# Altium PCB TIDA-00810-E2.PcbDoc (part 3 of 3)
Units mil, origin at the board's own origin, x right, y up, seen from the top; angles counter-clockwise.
Board outline 4527.56 x 3740.16 mil, 4 copper layers (Top Layer, Signal Layer 1, Signal Layer 2, Bottom Layer), stack 25.634 mil thick; 448 components, 198 nets, 1031 pads, 344 vias.
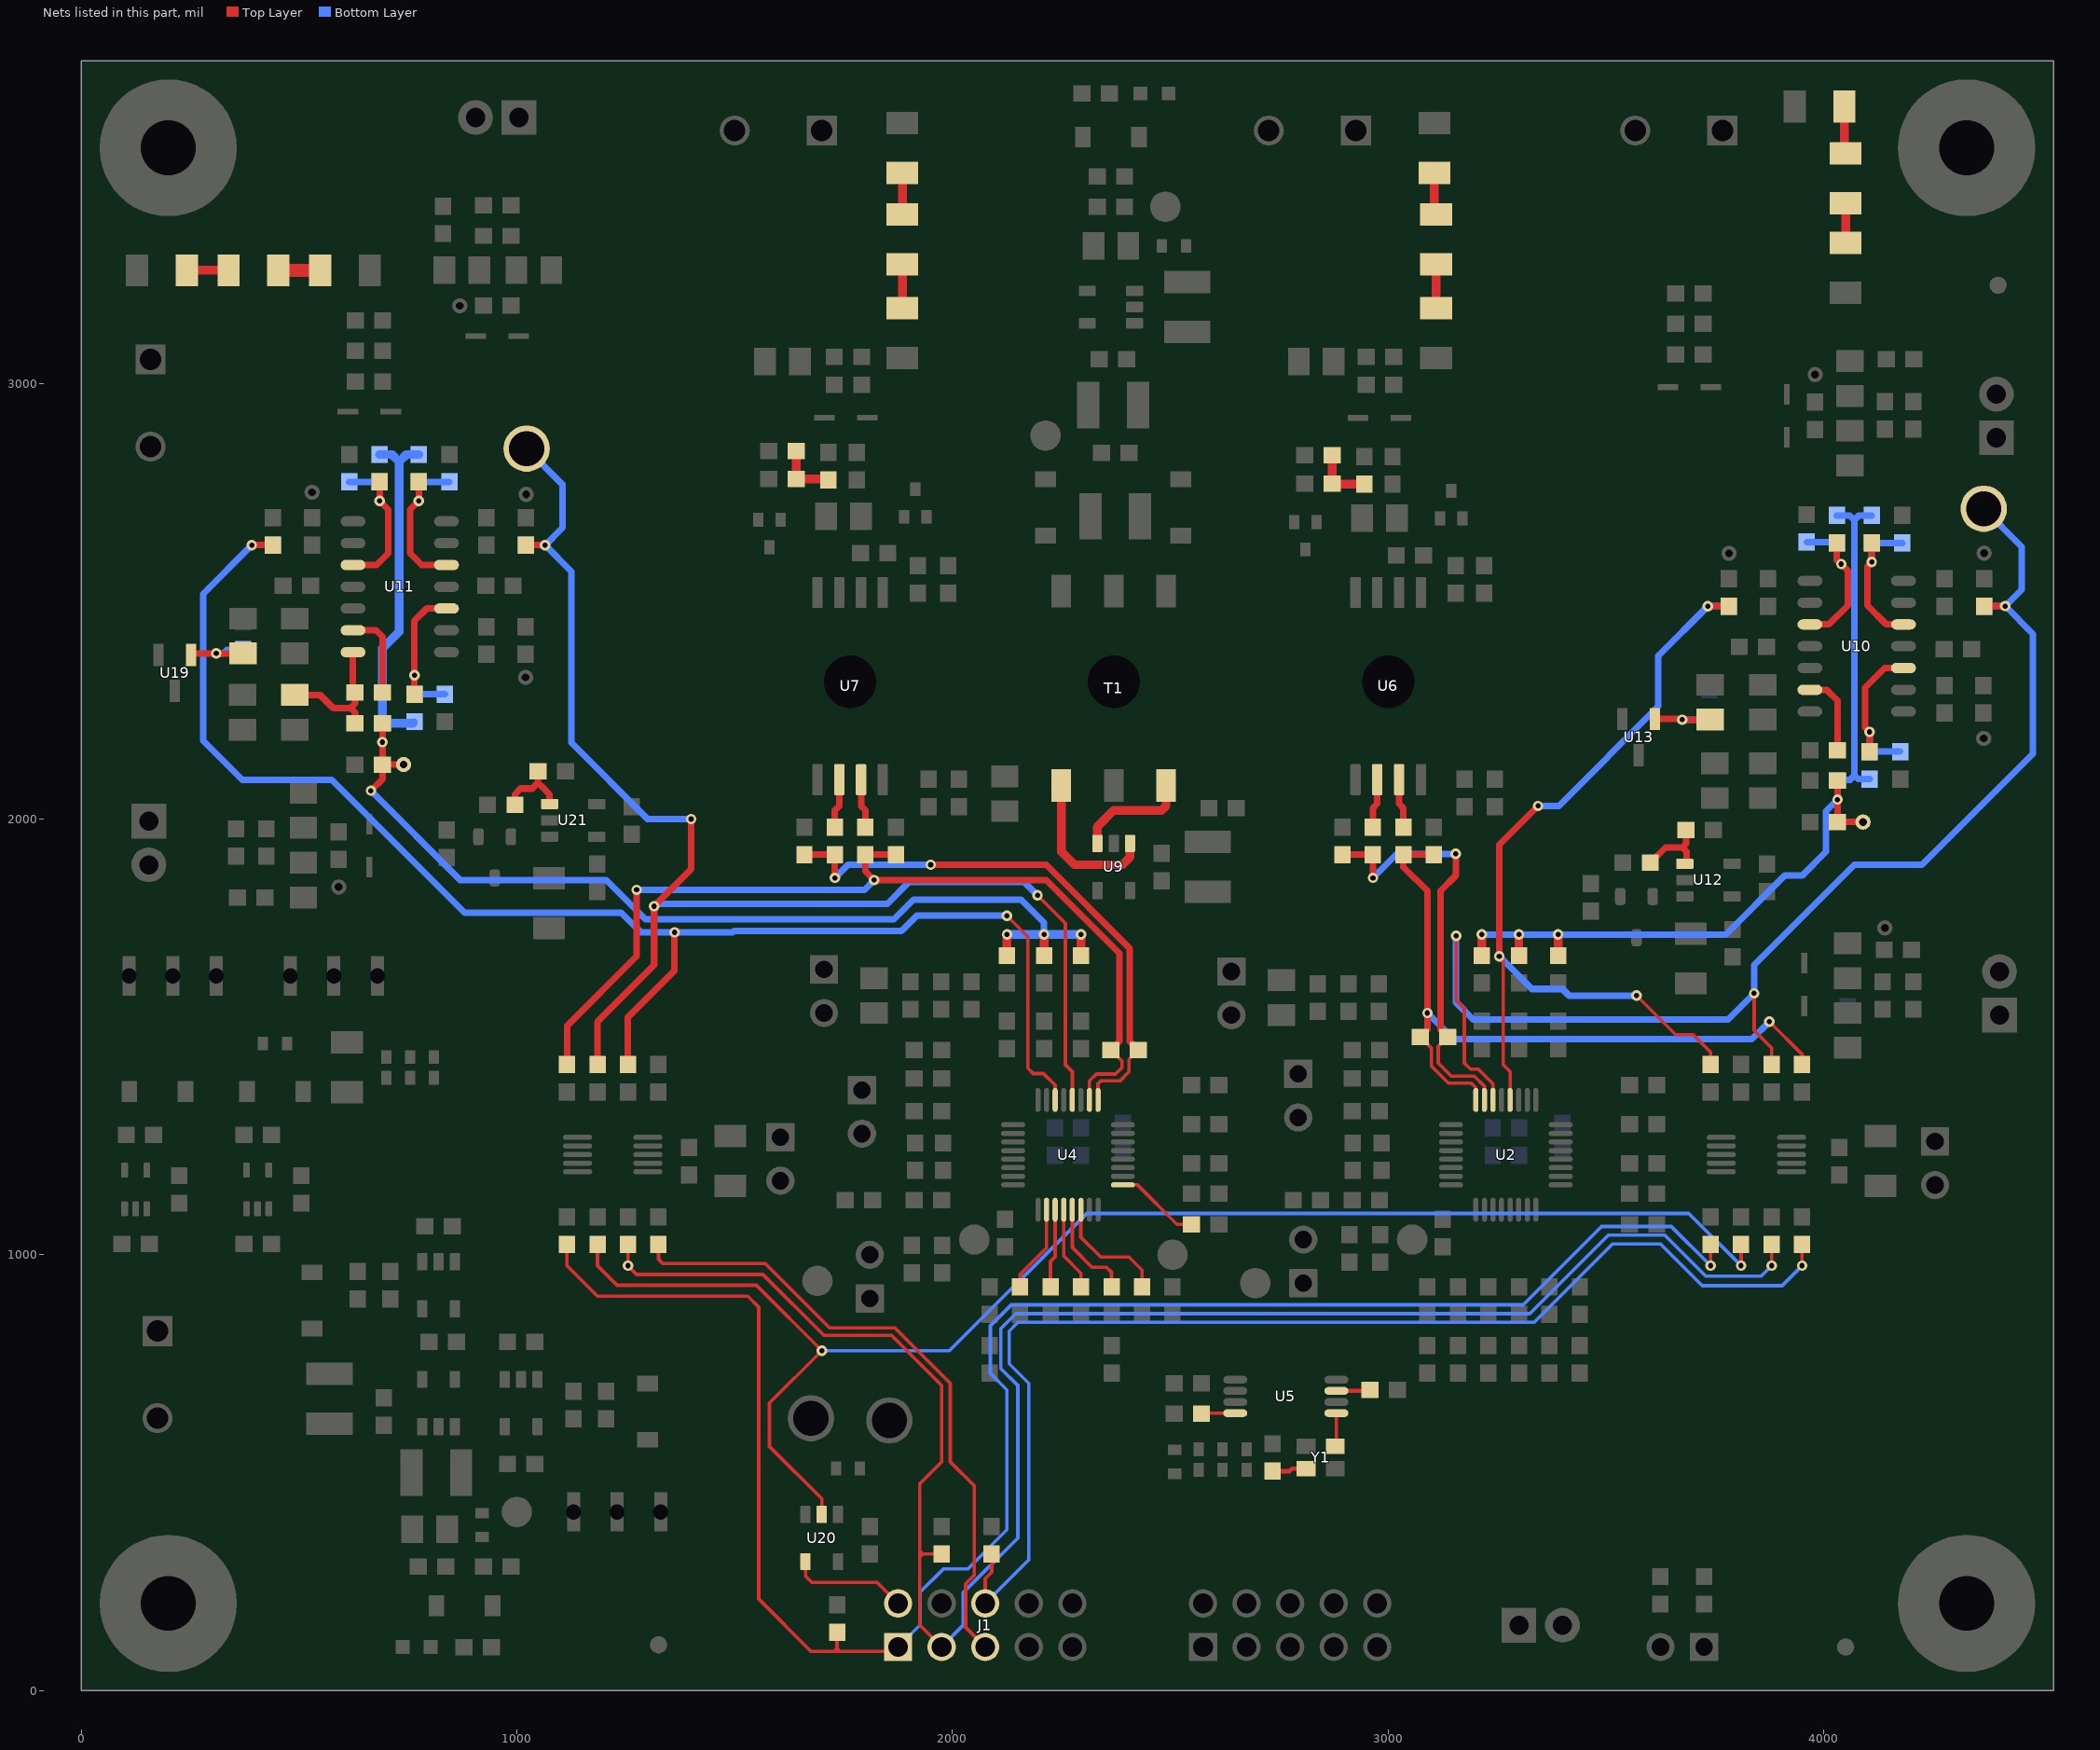
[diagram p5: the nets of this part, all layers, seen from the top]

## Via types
v1: diameter 24, hole 12, Top Layer to Bottom Layer, tented both sides, 309 vias
v2: diameter 32, hole 16, Top Layer to Bottom Layer, tented both sides, 35 vias

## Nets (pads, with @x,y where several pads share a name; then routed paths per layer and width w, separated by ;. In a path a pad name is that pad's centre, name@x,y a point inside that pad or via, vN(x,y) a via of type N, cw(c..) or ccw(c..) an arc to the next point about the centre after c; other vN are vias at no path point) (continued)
NetR39_2: R39.2 U4.22 | length 273.1
  Top Layer w8: U4.22@2294.59,1103.36 2294.59,1040.47 2340.06,995 2405,995 2435.07,964.93 R39.2@2435.07,926.49
NetR40_2: R40.2 U4.20 | length 193.4
  Top Layer w8: U4.20@2255.22,1103.36 2255.22,997.34 2295.07,957.5 R40.2@2295.07,926.49
NetR41_2: R41.2 U4.21 | length 247.1
  Top Layer w8: 2274.91,1030 2274.91,1016.65 ; U4.21@2274.91,1103.36 2274.91,1016.65 ; R41.2@2365.07,926.49 2365.07,959.93 2353.43,971.57 2319.99,971.57 2274.91,1016.65
NetR42_2: R42.2 U4.19 | length 181.2
  Top Layer w8: R42.2@2225.07,926.49 2225.07,949.18 2225.07,985 2235.54,995.47 2235.54,1000.47 2235.54,1010.47 U4.19@2235.54,1103.36
NetR43_2: R43.2 U4.18 | length 215.4
  Top Layer w8: R43.2@2155.07,930 R43.2@2155.07,926.49 2155.07,955 2165.07,965 ; 2158.12,958.05 2215.85,1015.79 U4.18@2215.85,1103.36
NetR44_1: R44.1 U4.25 | length 195
  Top Layer w8: U4.25@2391.05,1160.44 2424.62,1160.44 2515.07,1070 R44.1@2548.57,1070
NetR47_2: R47.2 U5.3 | length 81.4
  Top Layer w10: U5.3@2881.14,687.8 2881.35,688 2956.5,688 R47.2@2958.5,690 R47.2@2956.3,687.8
NetR48_2: R48.2 U5.8 | length 78
  Top Layer w8: R48.2@2571.5,635 2573.11,636.61 U5.8@2648.86,636.61
NetR49_2: R49.2 Y1.1 | length 79
  Top Layer w10: R49.2@2735,503.5 2773.5,503.5 2779.41,509.41 Y1.1@2811.54,509.41
NetR51_2: R51.2 R52.1 | length 98.6
  Top Layer w20: R51.2@3105.96,3493.98 3105.96,3401.12 R52.1@3110,3397.09
NetR52_2: R52.2 R53.1 | length 105.8
  Top Layer w20: R53.1@3110,3177.09 R52.2@3110,3282.91
NetR57_1: R57.1 U6.7 | length 113.1
  Top Layer w15: U6.7@3025,2090.43 3025,2035 3035,2025 R57.1@3035,1981.5
NetR58_1: R58.1 U6.6 | length 113.1
  Top Layer w15: R58.1@2965,1981.5 2965,2025 2975,2035 U6.6@2975,2090.43
NetR60_2: R60.2 R180.2 R184.2 | length 139.1
  Top Layer w20: R184.2@2871.5,2835 R180.2@2871.5,2770 2872.99,2768.5 R60.2@2945,2768.5
NetR61_2: R61.2 R62.1 | length 95.8
  Top Layer w20: R62.1@1885,3387.09 R61.2@1885,3482.91
NetR62_2: R62.2 R63.1 | length 100.8
  Top Layer w20: R63.1@1885,3172.09 R62.2@1885,3272.91
NetR66_1: R66.1 U7.7 | length 113.1
  Top Layer w15: U7.7@1790,2090.43 1790,2030 1800,2020 R66.1@1800,1981.5
NetR69_1: R69.1 U7.6 | length 113.1
  Top Layer w15: R69.1@1730,1981.5 1730,2020 1740,2030 U7.6@1740,2090.43
NetR71_2: R71.2 R181.2 R185.2 | length 139.1
  Top Layer w20: R185.2@1641.5,2845 R181.2@1641.5,2780 1713.5,2780 R71.2@1715,2778.5
NetR74_1: R74.1 R78.2 | length 109.1
  Top Layer w20: R74.1@4047.09,3635 4047.09,3530 R78.2@4050,3527.09
NetR76_1: R76.1 R80.2 | length 95.8
  Top Layer w20: R76.1@242.46,3259.39 R80.2@338.29,3259.39
NetR78_1: R78.1 R84.2 | length 90.8
  Top Layer w20: R84.2@4050,3322.09 R78.1@4050,3412.91
NetR80_1: R80.1 R87.2 | length 95.8
  Top Layer w30: R80.1@452.46,3259.39 R87.2@548.29,3259.39
NetR85_1: R85.1 R130.2 R178.2 U10.10 | length 381.1
  Top Layer w15: U10.10@3968.18,2446.56 4011.56,2446.56 4055,2490 4055,2570 v1(4040,2585) 4030,2595 R85.1@4030,2633.5
  Bottom Layer w15: R178.2@3961,2635.5 4028,2635.5 R130.2@4030,2633.5 4030,2595 v1(4040,2585)
NetR86_1: R86.1 R131.2 R179.2 U11.10 | length 377.6
  Top Layer w15: U11.10@623.88,2583.03 678.03,2583.03 705,2610 705,2710 v1(685,2730) R86.1@685,2773.5
  Bottom Layer w15: R179.2@615,2773.5 R131.2@685,2773.5 v1(685,2730)
NetR98_1: R98.1 R168.2 R174.2 U10.3 | length 373
  Top Layer w15: R98.1@4105,2154.57 v1(4105,2200) 4095,2210 4095,2301.56 4140,2346.56 U10.3@4182.75,2346.56
  Bottom Layer w15: v1(4105,2200) R168.2@4105,2154.57 R174.2@4175,2154.57
NetR99_1: R99.1 R169.2 R175.2 U11.3 | length 367.1
  Top Layer w15: R99.1@765,2286.5 v1(765,2330) 765,2455 793.03,2483.03 U11.3@838.45,2483.03
  Bottom Layer w15: v1(765,2330) R169.2@765,2286.5 R175.2@835,2286.5
NetR114_1: R114.1 R172.2 R176.2 U10.5 | length 361.9
  Top Layer w15: R114.1@4110,2633.5 v1(4110,2590) 4100,2580 4100,2490 4143.44,2446.56 U10.5@4182.75,2446.56
  Bottom Layer w15: v1(4110,2590) R172.2@4110,2633.5 R176.2@4180,2633.5
NetR115_1: R115.1 R173.2 R177.2 U11.5 | length 379.9
  Top Layer w15: R115.1@775,2773.5 v1(775,2730) 755,2710 755,2610 781.97,2583.03 U11.5@838.45,2583.03
  Bottom Layer w15: v1(775,2730) R173.2@775,2773.5 R177.2@845,2773.5
NetR116_1: R116.1 U10.13 | length 187.2
  Top Layer w15: U10.13@3968.18,2296.56 4006.51,2296.56 4031.5,2271.58 R116.1@4031.5,2158.07
NetR117_1: R117.1 U11.13 | length 202.1
  Top Layer w15: U11.13@623.88,2433.03 676.97,2433.03 691.5,2418.5 R117.1@691.5,2290
NetR117_2: R117.2 R129.1 R139.2 U11.14 | length 317.1
  Top Layer w15: R139.2@490,2285 548,2285 578,2255 621,2255 ; U11.14@623.88,2383.03 623.88,2294.62 R117.2@628.5,2290 628.5,2265.5 618,2255 628.5,2244.5 R129.1@628.5,2220
NetR119_2: R119.2 R127.2 U12.1 | length 175
  Top Layer w15: R127.2@3601.5,1900 3636.5,1935 3675,1935 ; U12.1@3680.87,1897.4 3685,1901.54 3685,1925 3675,1935 ; R119.2@3683.5,1975 3683.5,1943.5 3675,1935
NetR120_1: R120.1 R128.2 U21.1 | length 181.1
  Top Layer w15: R128.2@995.63,2032.05 995.63,2056.81 1008.82,2070 1035,2070 1048.5,2083.5 ; R120.1@1048.5,2110 1048.5,2083.5 ; U21.1@1079.13,2038.58 U21.1@1075,2034.45 1075,2057 1062.01,2069.99 1048.5,2083.5
NetR152_1: R152.1 R153.1 U13.1 | length 191.2
  Top Layer w15: U13.1@3612.4,2229.41 3673.66,2229.41 v1(3675,2228.07) R153.1@3738.62,2228.07
  Bottom Layer w15: v1(3675,2228.07) 3732.09,2228.07 R152.1@3737.3,2233.29
NetR155_1: R155.1 R156.1 U19.1 | length 185.6
  Top Layer w15: U19.1@252.4,2376.34 256.06,2380 v1(310,2380) R156.1@371.46,2380
  Bottom Layer w15: v1(310,2380) 326.46,2380 334.96,2388.5 R155.1@371.46,2388.5
NetT1_1: T1.1 U9.1 | length 361.2
  Top Layer w20: T1.1@2249.92,2077.36 2249.92,1925.08 2280,1895 2390,1895 2407.4,1912.4 U9.1@2407.4,1944.13
NetT1_3: T1.3 U9.3 | length 262.9
  Top Layer w20: U9.3@2332.6,1944.13 2332.6,1982.6 2370,2020 2480,2020 2490.08,2030.08 T1.3@2490.08,2077.36
NetU5_1: U5.1 Y1.3 | length 77.1
  Top Layer w8: Y1.3@2878.46,560.59 2881.14,563.27 U5.1@2881.14,636.61
PD_OUT1: C57.1 R81.2 R144.2 U2.4 | length 2071.1
  Top Layer w8: v1(3255,1685) 3264,1676 3264,1436.06 3279.91,1420.16 U2.4@3279.91,1355.33 ; v1(3570,1595) 3660,1505 3700,1505 3740.13,1464.87 R144.2@3740.13,1436.49
  Top Layer w15: v1(3255,1685) 3255,1941 v1(3344,2030) ; v1(3733.8,2488.29) R81.2@3782.3,2488.29
  Bottom Layer w15: v1(3255,1685) 3330,1610 3400,1610 3415,1595 v1(3570,1595) ; v1(3344,2030) 3391.5,2030 3620,2258.5 3620,2374.49 v1(3733.8,2488.29) C57.1@3782.3,2488.29
PD_OUT2: C58.1 R83.2 R150.2 U4.6 | length 3467
  Top Layer w8: v1(2125,1778) 2173,1730 2173,1428 2185,1416 2209,1416 2235.54,1389.46 U4.6@2235.54,1355.33
  Top Layer w15: v1(391.5,2628.5) R83.2@440,2628.5 ; R150.2@1255.07,1436.49 1255.07,1545.07 1362,1652 v1(1362,1740) v1@1362,1742
  Bottom Layer w15: C58.1@440,2628.5 v1(391.5,2628.5) 280,2517.01 280,2180 370,2090 575,2090 880,1785 1240,1785 1285,1740 v1(1362,1740) 1495.47,1740 1498.47,1743 1883,1743 1918,1778 v1(2125,1778)
ROGO_1_OUT: C74.1 R111.2 R146.2 TP4.1 U2.6 | length 3123.3
  Top Layer w8: v1(3156,1732) 3156,1584 3175,1565 3175,1440 3189,1426 3207.07,1426 3240.54,1392.53 U2.6@3240.54,1355.33 ; v1(3840,1600) 3840,1515 3880.13,1474.87 R146.2@3880.13,1436.49
  Top Layer w15: R111.2@4367.87,2488.5 v1(4416.37,2488.5)
  Bottom Layer w15: v1(3156,1732) 3156,1579 3195,1540 3780,1540 v1(3840,1600) 3840,1665 4070,1895 4225,1895 4480,2150 4480,2424.88 v1(4416.37,2488.5) ; TP4.1@4367,2712 4454,2625 4454,2526.13 v1(4416.37,2488.5) ; C74.1@4367.87,2488.5 v1(4416.37,2488.5)
ROGO_2_OUT: C75.1 R113.2 R147.2 TP8.1 U4.4 | length 3255.8
  Top Layer w8: v1(2195,1825) 2259,1761 2259,1436.06 2274.91,1420.16 U4.4@2274.91,1355.33
  Top Layer w15: R113.2@1021.32,2628.5 v1(1064.82,2628.5) ; R147.2@1185.07,1436.49 1185.07,1535.07 1315,1665 v1(1315,1800) 1400,1885 v1(1400,2000)
  Bottom Layer w15: C75.1@1021.32,2628.5 v1(1064.82,2628.5) ; TP8.1@1022.5,2850 1105,2767.5 1105,2668.68 v1(1064.82,2628.5) ; v1(1315,1800) 1320,1805 1850,1805 1900,1855 2165,1855 v1(2195,1825) ; v1(1400,2000) 1300,2000 1125,2175 1125,2568.33 v1(1064.82,2628.5)
SAR1_CS#: J1.6 R4.2 R162.1 | length 2815
  Top Layer w8: J1.6@2075,200 2075,256.75 2090,271.75 R162.1@2090,313.5 ; v1(3950.07,975) R4.2@3950.07,1023.5
  Bottom Layer w8: J1.6@2075,200 2175,300 2175,705 2130,750 2130,825 2150,845 3335,845 3515,1025 3625,1025 3721,929 3904.07,929 v1(3950.07,975)
SAR2_CS#: J1.5 R27.2 | length 1476.3
  Top Layer w8: R27.2@1325,1023.5 1325,990 1335,980 1570,980 1717.5,832.5 1867.5,832.5 1995,705 1995,525 2050,470 2050,265 2030,245 2030,145 J1.5@2075,100
SAR_DIN: J1.3 R1.2 R24.2 R163.1 | length 4360.5
  Top Layer w8: R24.2@1255,1023.5 v1(1255,975) 1275,955 1565,955 1705,815 1860,815 1975,700 1975,525 1925,475 1925,150 J1.3@1975,100 ; 1925,307.01 1931.5,313.5 ; 1925,320 1931.5,313.5 ; R163.1@1975,313.5 1931.5,313.5 ; v1(3880.07,975) R1.2@3880.07,1023.5
  Bottom Layer w8: v1(1255,975) v1(1255,975) ; J1.3@1975,100 2024,149 2024,224 2150,350 2150,700 2111,739 2111,831 2145,865 3325,865 3505,1045 3635,1045 3729.03,950.97 3856.03,950.97 v1(3880.07,975)
SAR_DOUT: R2.1 R25.1 U20.2 | length 3458.3
  Top Layer w8: R25.1@1185.07,1023.5 1185.07,974.93 1230,930 1550,930 v1(1700,780) 1580,660 1580,560 1700,440 U20.2@1700,404.13 ; v1(3810.07,975) R2.1@3810.07,1023.5
  Bottom Layer w8: v1(1700,780) 1993,780 2308,1095 3690.06,1095 v1(3810.07,975)
SAR_DOUT_L: J1.2 U20.4 | length 271.7
  Top Layer w8: U20.4@1662.6,295.87 1662.6,262.4 1677,248 1827,248 J1.2@1875,200
SAR_SCLK: J1.1 R3.2 R26.2 R140.1 | length 4350.4
  Top Layer w8: R26.2@1115,1023.5 1115,975 1185,905 1530,905 1555,880 1555,210 1675,90 1728,90 ; R140.1@1735,133.5 1735,97 ; J1.1@1875,100 1865,90 1742,90 ; v1(3740.07,975) R3.2@3740.07,1023.5 ; 1728,90 1742,90 ; 1728,90 1735,97 ; 1735,97 1742,90
  Bottom Layer w8: J1.1@1875,100 1926,151 1926,226 1979,279 2035,279 2125,369 2125,690 2087,728 2087,837 2135,885 3310,885 3490,1065 3650,1065 v1(3740.07,975) v1(3740.07,975)
VOUT1_N: C105.1 C110.1 R58.2 U2.7 | length 1006
  Top Layer w8: C105.1@3136.56,1500 3115.07,1478.5 3115.07,1439.93 3145,1410 3197.69,1410 3220.98,1386.71 3220.85,1386.58 U2.7@3220.85,1355.33
  Top Layer w15: C110.1@2895,1918.5 R58.2@2965,1918.5 v1(2965,1865) ; C105.1@3136.56,1500 3120,1516.56 3120,1835 3155,1870 v1(3155,1920)
  Bottom Layer w15: v1(2965,1865) 3020,1920 v1(3155,1920)
VOUT1_P: C105.2 C111.1 R57.2 R145.2 U2.8 | length 1702.5
  Top Layer w8: C105.2@3073.57,1500 3099.07,1474.5 3099.07,1433.31 3138.37,1394 3191.07,1394 3201.17,1383.9 U2.8@3201.17,1355.33 ; v1(3875,1535) 3950.13,1459.87 R145.2@3950.13,1436.49
  Top Layer w15: C105.2@3073.57,1500 3090,1516.43 v1(3090,1555) 3090,1835 3035,1890 R57.2@3035,1918.5 C111.1@3105,1918.5
  Bottom Layer w15: v1(3090,1555) 3150,1495 3835,1495 v1(3875,1535)
VOUT2_N: C106.1 C112.1 R69.2 U4.1 | length 1312.4
  Top Layer w8: U4.1@2333.96,1355.33 2333.96,1392.9 2340.07,1399 2384.07,1399 2405.07,1420 2405.07,1448.5 C106.1@2426.56,1470
  Top Layer w15: C112.1@1660,1918.5 R69.2@1730,1918.5 v1(1730,1865) ; v1(1950,1895) 2215,1895 2407.13,1702.87 2407.13,1489.43 C106.1@2426.56,1470
  Bottom Layer w15: v1(1730,1865) 1760,1895 v1(1950,1895)
VOUT2_P: C106.2 C113.1 R66.2 R148.2 U4.2 | length 2205.6
  Top Layer w8: U4.2@2314.28,1355.33 2314.28,1399.21 2330.07,1415 2374.07,1415 2389.07,1430 2389.07,1444.5 C106.2@2363.57,1470
  Top Layer w15: R148.2@1115.07,1436.49 1115.07,1525.07 1275,1685 v1(1275,1837.63) ; C113.1@1870,1918.5 R66.2@1800,1918.5 1800,1880 v1(1820,1860) 2215,1860 2383,1692 2383,1489.43 C106.2@2363.57,1470 C106.2@2363.57,1472.57
  Bottom Layer w15: v1(1275,1837.63) 1797.63,1837.63 v1(1820,1860)
VREF_ADC1: C76.2 R118.1 R126.2 R130.1 R136.1 R137.1 R138.1 R168.1 R172.1 TP21.1 | length 2100.5
  Top Layer w15: R118.1@4030,1991.58 R118.1@4031.5,1993.07 ; R126.2@4031.5,2088.07 v1(4031.5,2044.57) R118.1@4031.5,1993.07 ; TP21.1@4090,1993.07 R118.1@4031.5,1993.07
  Top Layer w20: R138.1@3215.07,1686.5 v1(3215.07,1735) ; R137.1@3300.07,1686.5 v1(3300.07,1735) ; R136.1@3390.07,1686.5 v1(3390.07,1735)
  Bottom Layer w15: v1(3215.07,1735) v1(3300.07,1735) v1(3390.07,1735) 3775,1735 3910,1870 3950,1870 4005,1925 4005,2018.07 v1(4031.5,2044.57) C76.2@4031.5,2088.07 4033.42,2090 4060,2090 4070,2100 ; R130.1@4030,2696.5 4059.7,2696.5 4070,2686.2 ; R168.1@4105,2091.58 4078.42,2091.58 4070,2100 ; R172.1@4110,2696.5 4080.3,2696.5 4070,2686.2 ; 4070,2100 4070,2686.2
VREF_ADC2: C77.2 R121.1 R129.2 R131.1 R158.1 R159.1 R160.1 R169.1 R173.1 TP22.1 | length 3105.1
  Top Layer w15: v1(665,2065) 691.5,2091.5 R121.1@691.5,2125 ; R129.2@691.5,2220 v1(691.5,2176.5) R121.1@691.5,2125 ; TP22.1@740,2125 R121.1@691.5,2125
  Top Layer w20: R160.1@2125.07,1686.5 v1(2125.07,1735) ; R159.1@2210.07,1686.5 v1(2210.07,1735) ; R158.1@2295.07,1686.5 v1(2295.07,1735)
  Bottom Layer w15: v1(665,2065) 870,1860 1205,1860 1295,1770 1865,1770 1910,1815 2157.3,1815 2210.07,1762.23 v1(2210.07,1735) ; v1(691.5,2176.5) C77.2@691.5,2220 ; R169.1@761.5,2220 765,2220 R169.1@765,2223.5
  Bottom Layer w20: R131.1@685,2836.5 713.5,2836.5 730,2820 ; R169.1@761.5,2220 C77.2@691.5,2220 691.5,2391.5 730,2430 730,2820 ; R173.1@775,2836.5 746.5,2836.5 730,2820 ; v1(2125.07,1735) v1(2210.07,1735) v1(2295.07,1735)
pads on no net: D1.3 D2.3 D3.3 D4.3 D5.3 D6.3 D7.3 D8.3 D13.2 D14.2 FID1.1 FID2.1 FID3.1 FID4.1 FID5.1 FID6.1 H1.1 H2.1 H3.1 H4.1 H5.0 H6.0 H7.0 H8.0 J1.8 LBL1.0 U2.24 U2.26 U4.24 U4.26 U5.5 U5.7 U8.4 U8.5 U13.3 U14.4 U14.5 U19.3 U20.1

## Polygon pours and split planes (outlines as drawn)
-2P5V on Top Layer "-2P5V_L01_P024" (solid, remove dead copper, pour order 24): 1010,630 1020,640 1355,640 1370,625 1370,560 1370,540 1355,525 1125,525 1085,565 1020,565 1010,575
3.3V on Top Layer "3.3V_L01_P006" (solid, remove dead copper, pour order 6): 325,1435 340,1450 385,1450 395,1440 395,1210 395,1170 385,1160 335,1160 325,1170
AGND on Top Layer "AGND_L01_P010" (solid, remove dead copper, pour order 10): 870,1400 855,1415 710,1415 685,1415 680,1420 470,1420 460,1410 460,1340 450,1330 430,1330 420,1320 420,1245 425,1240 470,1240 560,1240 570,1230 570,1160 555,1145 470,1145 460,1135 460,1080 450,1070 430,1070 420,1060 420,1025 420,1003 420,980 430,970 460,970 500,1010 625,1010 635,1020 635,1230 645,1240 855,1240 870,1255
+5V on Top Layer "+5V_L01_P020" (solid, remove dead copper, pour order 20): 970,250 915,250 900,235 900,150 915,135 1040,135 1060,155 1060,330 1050,340 980,340 970,330
NetC80_2 on Top Layer "NETC80_2_L01_P016" (solid, remove dead copper, pour order 16): 850,645 850,440 860,430 925,430 935,440 935,635 915,655 860,655
AGND on Top Layer "AGND_L01_P014" (solid, remove dead copper, pour order 14): 50,683.62 71.37,705 375,705 415,665 630,665 650,645 650,625 780,625 790,615 790,590 790,575 775,560 775,510 775,330 780,325 790,315 790,285 790,250 795,245 855,245 860,240 860,150 850,140 770,140 760,140 680,140 500,140 475,165 475,220 475,450 450,475 445,480 280,480 70,480 50,500
+2P5V on Top Layer "+2P5V_L01_P012" (solid, remove dead copper, pour order 12): 50,1442.05 62.95,1455 125,1455 160,1455 165,1450 165,1365 125,1325 125,1175 110,1160 60,1160 50,1170
AVCC_3.3 on Top Layer "AVCC_3.3_L01_P008" (solid, remove dead copper, pour order 8): 540,1535 555,1550 845,1550 865,1530 865,1450 855,1440 695,1440 670,1440 550,1440 540,1450
DC_IN on Top Layer "DC_IN_L01_P000" (solid, remove dead copper, pour order 0): 103,1117 103,1047 110,1040 110,965 135,940 230,940 320,940 330,950 330,1120 340,1130 380.01,1130 390,1120.01 390,945 410,925 510,925 565,870 565,855 665,755 690,730 715,730 765,680 830,680 835,675 835,655 830,650 745,650 675,650 645,680 440,680 365,755 65,755 50,770 50,1115 60,1125 95,1125
AGND on Top Layer "AGND_L01_P004" (solid, remove dead copper, pour order 4): 572.5,912.5 580,920 795,920 800,915 800,830 815,815 815,765 805,755 705,755 572.5,887.5
AGND on Top Layer "AGND_L01_P002" (solid, remove dead copper, pour order 2): 195,1440 195,1340 185,1330 160,1330 150,1320 150,1239.99 160,1230 260,1230 270,1220 270,1160 250,1140 190,1140 180,1130 180,1070 175,1065 145,1065 135,1055 135,1030 135,975 145,965 295,965 305,975 305,1440 290,1455 210,1455
NetC94_1 on Top Layer "NETC94_1_L01_P022" (solid, remove dead copper, pour order 22): 995,840 995,765 1020,740 1020,675 1010,665 940,665 915,690 915,740 905,750 850,750 840,760 840,825 865,850 985,850
AGND on Top Layer "AGND_L01_P026" (solid, remove dead copper, pour order 26): 1020,840 1020,775 1040,755 1040,675 1050,665 1355,665 1370,680 1370,845 1365,850 1030,850
AVSS on Bottom Layer "AVSS_L04_P028" (solid, remove dead copper, pour order 28): 1700,1200 1790,1110 2110,1110 2140,1110 2163.7,1133.7 2163.69,1313.69 2178.84,1328.84 2338.84,1328.84 2470,1460 2660,1460 2685,1435 2685,1205 2740,1150 3155,1150 3165,1160 3165,1310 3183.84,1328.84 3353.84,1328.84 3385,1360 3385,1420 3365,1440 3145,1440 3060,1525 3060,1695 3015,1740 2360,1740 2260,1640 1890,1640 1700,1450
GND_VDC on Signal Layer 1 "GND_VDC_L02_P030" (solid, remove dead copper, pour order 30): 1400,3675 1425,3700 1700,3700 3250,3700 3275,3675 3275,2500 3250,2475 3125,2475 1425,2475 1400,2500 1400,3675
AGND on Signal Layer 1 "AGND_L02_P038" (solid, remove dead copper, pour order 38): 50,3300 75,3325 350,3325 375,3325 400,3350 400,3675 425,3700 625,3700 1150,3700 1175,3675 1175,3550 1175,2150 1200,2125 1325,2125 3450,2125 3475,2150 3475,2225 3475,3675 3500,3700 3650,3700 4100,3700 4125,3675 4125,3600 4125,3375 4150,3350 4175,3325 4300,3325 4450,3325 4475,3300 4475,3150 4475,425 4450,400 4425,400 4125,400 4100,375 4100,175 4100,75 4075,50 3800,50 3600,50 3575,75 3575,475 3625,525 3625,875 3600,900 3600,1425 3575,1450 3440,1450 3300,1310 3300,1210 3260,1170 3160,1170 3115,1125 3050,1125 2625,1125 2600,1150 2600,1450 2575,1475 2550,1475 2460,1475 2317.5,1332.5 2295,1310 2295,1190 2265,1160 2145,1160 1960,1160 1950,1150 1850,1050 1850,975 1850,900 1775,825 1750,800 1750,625 1750,75 1725,50 1350,50 450,50 425,75 425,250 425,400 400,425 225,425 75,425 50,450
GND on Signal Layer 1 "GND_L02_P034" (solid, remove dead copper, pour order 34): 2465,1450 2550,1450 2575,1425 2575,1150 2625,1100 3125,1100 3170,1145 3274.87,1145 3325,1195.13 3325,1300 3450,1425 3575,1425 3575,1235 3575,875 3600,850 3600,550 3550,500 3550,375 3550,250 3550,75 3525,50 3275,50 3075,250 2380,250 2360,230 2360,160 2350,150 2250,150 2225,175 2225,225 2200,250 1800,250 1775,275 1775,800 1850,875 1875,900 1875,1025 1985,1135 2150,1135 2280,1135 2320,1175 2320,1305
+5.0V_VDC on Signal Layer 2 "+5.0V_VDC_L03_P032" (solid, remove dead copper, pour order 32): 1450,3550 1450,3625 1475,3650 1575,3650 3200,3650 3225,3625 3225,3550 3225,2755.98 3235.32,2745.66 3250,2730.98 3250,2650 3251.39,2650 3275,2626.39 3275,2525 3275,2500 3250,2475 3245.51,2475 3200,2475 3175,2500 3150,2525 3050,2525 2700,2525 2100,2525 2075,2500 1975,2500 1950,2525 1875,2525 1475,2525 1450,2550
AVDD on Signal Layer 2 "AVDD_L03_P040" (solid, remove dead copper, pour order 40): 125,3225 150,3250 350,3250 450,3250 475,3275 475,3350 475,3600 500,3625 850,3625 1075,3625 1100,3600 1100,3250 1100,2075 1125,2050 1300,2050 1775,2050 3525,2050 3550,2075 3550,3600 3575,3625 3775,3625 4025,3625 4050,3600 4050,3275 4075,3250 4375,3250 4400,3225 4400,1875 4350,1825 4325,1800 3825,1800 3650,1800 3475,1625 2400,1625 825,1625 750,1700 675,1700 650,1700 625,1675 625,1550 600,1525 375,1525 150,1525 125,1550 125,3225
AVCC_3.3 on Signal Layer 2 "AVCC_3.3_L03_P042" (solid, remove dead copper, pour order 42): 125,1475 150,1500 400,1500 600,1500 625,1500 650,1525 650,1575 650,1650 675,1675 725,1675 775,1625 800,1600 925,1600 1900,1600 3500,1600 3625,1725 3675,1775 4375,1775 4400,1775 4425,1750 4450,1725 4450,1600 4450,1575 4400,1525 4400,575 4400,450 4375,425 4250,425 4125,425 4100,400 4100,300 4100,150 4075,125 3675,125 3650,125 3575,50 2875,50 1350,50 1275,125 1175,125 500,125 475,150 475,450 450,475 150,475 125,500

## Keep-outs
Keep-Out Layer:
  lines w10: 25,25 4502.56,25 4502.56,3715.16 25,3715.16 25,25

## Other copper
Top Layer:
  text ".Layer_Name" at -50,-1200 h60
Signal Layer 1:
  text "GND" at -25,-1200 h60
Signal Layer 2:
  pour cut-out: 1800,250 1800,50 2350,50 2350,250 2325,275 1825,275
  pour cut-out: 2500,250 2500,50 3050,50 3050,250 3025,275 2525,275
  text "PWR" at -25,-1200 h60
Bottom Layer:
  text ".Layer_Name" at -25,-1200 h60
Multi-Layer:
  pour cut-out: 1375,3740.16 1200,3740.16 1200,2150 3450.62,2150 3450.62,3740.16 3300,3740.16 3300,2450 1375,2450 1375,3730.15

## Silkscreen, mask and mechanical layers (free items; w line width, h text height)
Top Overlay:
  circle w10: c1605,2725 r8
  circle w10: c1865,2660 r8
  circle w10: c3095,2655 r8
  circle w10: c2835,2715 r8
  circle w10: c1735,450 r8
  circle w10: c4185,2205 r8
  circle w10: c3680,1935 r5
  circle w10: c1044.13,2060.05 r8
  circle w10: c55,1110 r8
  circle w10: c335,1110 r8
  circle w10: c905,980 r8
  circle w10: c1050,755 r8
  circle w10: c740,605 r8
  circle w10: c2930.5,636.5 r10
  circle w10: c3380,1355 r10
  circle w10: c2375,1355 r10
  circle w10: c840,2340 r10
  lines w6: 330,2150 429,2150 450,2171 ; 405,2515 410,2515 431,2494 450,2494 ; 940,2285 870,2285 ; 1187.5,2947.5 1022.5,2947.5 ; 1635,2545 1660,2570 1747.22,2570 1760.02,2582.8 ; 1660,2895 1675,2895 1687.8,2882.2 1687.8,2869.98 ; 2090,1170 2025,1170 ; 2423.49,3377.73 2446.27,3377.73 2463,3361 2520,3361 ; 2860,2605 2905,2650 2906,2650 ; 2870,2530 2890,2550 2890,2610 2912.27,2632.27 2990.02,2632.27 ; 2905,2885 2917.8,2872.2 2917.8,2859.98 ; 3525,1465 3445,1465 ; 3620,2310 3650,2310 3670,2330 3695,2330 ; 3635,1980 3640,1975 3640,1935 3653.98,1921.02 3671.02,1921.02 ; 3665,2370 3690,2370 3705,2355 3807.07,2355 3820,2342.07 ; 3690,940 3500,940 ; 3721.5,2653.5 3876.5,2653.5 ; 3970,1840 3970,1920 ; 870,2285 880,2275 880,2295 870,2285 ; 1022.5,2947.5 1032.5,2937.5 1032.5,2957.5 1022.5,2947.5 ; 2025,1170 2035,1160 2035,1180 2025,1170 ; 3445,1465 3455,1455 3455,1475 3445,1465 ; 3500,940 3510,930 3510,950 3500,940 ; 3876.5,2653.5 3866.5,2663.5 3866.5,2643.5 3876.5,2653.5 ; 3970,1920 3980,1910 3960,1910 3970,1920 ; 555,2750 575,2730 875,2730 885,2740 885,2800 910,2825 910,2890 950,2930 1185,2930 1195,2940 1195,3080 1045,3080 865,2900 570,2900 555,2885 555,2750
  text "'.PRJ_Number'.PCB_Rev" at 3825,800 h72.83
  text ".Layer_Name" at -50,-1200 h60
Bottom Overlay:
  circle w10: c1555,2770 r8
  circle w10: c1940,2650 r8
  circle w10: c2785,2760 r8
  circle w10: c3170,2650 r8
  text ".Layer_Name" at -25,-1200 h60
Top Paste:
  text ".Layer_Name" at -60.48,-1203.85 h60
Bottom Paste:
  text ".Layer_Name" at -60.48,-1203.85 h60
Top Solder:
  text ".Layer_Name" at -25,-1200 h60
Bottom Solder:
  text ".Layer_Name" at -25,-1200 h60
Drill Guide:
  text ".Layer_Name" at -60.48,-1203.85 h60
M1 Board Outline:
  the board outline again, w10
M2 Board Dimensions:
  rectangle: -512.48,-755.86 -137.48,-630.86
  rectangle: -637.48,-630.86 -512.48,-505.86
  lines w7: -637.48,-630.86 362.52,-630.86 ; -512.48,-755.86 -512.48,-505.86 ; -387.48,-755.86 -387.48,-505.86 ; -137.48,-755.86 -137.48,-505.86 ; 112.52,-755.86 112.52,-505.86 ; -637.48,-755.86 -637.48,-505.86 362.52,-505.86 362.52,-755.86 -637.48,-755.86
M3 3D STEP Top:
  text ".Layer_Name" at -60.48,-1203.85 h60
M4 3D STEP Bottom:
  text ".Layer_Name" at -60.48,-1203.85 h60
M5 Assembly Top:
  circle w10: c1605,2720 r4.47
  circle w10: c2805.53,920 r10.53
  circle w10: c2790.53,1435 r10.53
  circle w10: c2640.53,1670 r10.53
  circle w10: c1705.53,1670 r10.53
  circle w10: c4255.53,1270 r10.53
  circle w10: c1790.53,1395 r10.53
  circle w10: c1605.53,1285 r10.53
  circle w10: c1810.53,885 r10.53
  circle w10: c3745.53,100 r10.53
  circle w10: c2570.53,145 r10.53
  circle w10: c1865.53,135 r10.53
  circle w10: c3120.53,2655 r4.47
  circle w10: c2834.47,2715 r4.47
  circle w10: c1890.53,2660 r4.47
  circle w10: c2435.53,3140 r4.47
  circle w10: c3646.32,2229.41 r4.47
  circle w10: c3660.53,1895 r4.47
  circle w10: c3605.53,1840 r4.47
  circle w10: c3920,1165 r4.47
  circle w10: c2405.53,1970 r4.47
  circle w10: c1735.53,425 r4.47
  circle w10: c1300,1190 r7.07
  circle w10: c783.53,584 r4.47
  circle w10: c1047.53,733 r4.47
  circle w10: c856.53,1005 r4.47
  circle w10: c380.53,1086 r4.47
  circle w10: c99.53,1086 r4.47
  circle w10: c1050,2035 r4.47
  circle w10: c985,1975 r4.47
  circle w10: c283,2376 r5
  lines w8: 155.94,2335 155.94,2307.44 187.44,2307.44 ; 242.56,2307.44 274.06,2307.44 274.06,2335 ; 3515.94,2188.07 3515.94,2160.51 3547.44,2160.51 ; 3602.56,2160.51 3634.06,2160.51 3634.06,2188.07 ; 1188.57,1167.01 1251.56,1167.01 1251.56,1292.99 1188.57,1292.99 1188.57,1167.01 ; 3813.64,1167.01 3876.63,1167.01 3876.63,1292.99 3813.64,1292.99 3813.64,1167.01
  lines w10: -929.48,-1275.53 5670.52,-1275.53 ; -929.48,-1072.19 5672.52,-1072.19 ; -929.48,-868.86 -929.48,-1478.86 3075.52,-1478.86 5672.52,-1478.86 5672.52,-868.86 -928.98,-868.86 -928.98,-1478.86 646.52,-1478.86 ; 1535.52,-1478.86 1535.52,-868.86 ; 2802.52,-1072.19 2802.52,-868.86 ; 3642.52,-1072.19 3642.52,-868.86 ; 4264.52,-1485.36 4264.52,-1282.53
  text "ASSEMBLY VARIANT:" at 515.52,-779.36 h25
  text ".VariantName" at 1551.52,-779.36 h25
  text "PCB VIEWED FROM TOP SIDE" at -865.98,-1001.03 h25
  text "BOARD #:" at 1610.52,-1001.03 h25
  text ".PRJ_Number" at 2156.02,-1001.03 h25
  text "REV:" at 3000.52,-1001.03 h25
  text ".PCB_Rev" at 3292.02,-1001.03 h25
  text "SVN REV:" at 3838.52,-1001.03 h25
  text ".VersionControl_RevNumber" at 4344.52,-1001.03 h25
  text "IGNORE ->" at 1591,-1188 h25
  text "M5 Assembly Top" at -25,-1200 h60
  text "LAYER NAME =" at -865.98,-1203.85 h60
  text "PLOT NAME =" at -865.98,-1409.69 h25
  text ".plot_File_Name" at -60.48,-1409.69 h25
  text "GENERATED    :" at 1612.52,-1409.69 h25
  text ".Print_Date" at 2482.02,-1409.69 h25
  text ".Print_Time" at 3211.02,-1409.69 h25
  text "TEXAS INSTRUMENTS" at 4475.52,-1409.69 h25
M6 Assembly Bottom:
  circle w10: c1555,2720 r5
  circle w10: c1940,2665 r5
  circle w10: c2785,2715 r5
  circle w10: c3170,2660 r5
  lines w10: -929.98,-1072.69 5672.02,-1072.69 ; -927.98,-1276.03 5672.02,-1276.03 ; 478.02,-1485.86 478.02,-1283.03 ; 1100.02,-1072.69 1100.02,-869.36 ; 1940.02,-1072.69 1940.02,-869.36 ; 3207.02,-1479.36 3207.02,-869.36 ; 4096.02,-1479.36 5671.52,-1479.36 5671.52,-869.36 -929.98,-869.36 -929.98,-1479.36 1667.02,-1479.36 5672.02,-1479.36 5672.02,-869.36
  text "COMPONENTS MARKED 'DNP' SHOULD NOT BE POPULATED." at 5464.52,-663.36 h25
  text ".VariantName" at 4420.52,-779.36 h25
  text "ASSEMBLY VARIANT:" at 5459.52,-779.36 h25
  text ".VersionControl_RevNumber" at 398.02,-1001.53 h25
  text "SVN REV:" at 904.02,-1001.53 h25
  text ".PCB_Rev" at 1450.52,-1001.53 h25
  text "REV:" at 1742.02,-1001.53 h25
  text ".PRJ_Number" at 2586.52,-1001.53 h25
  text "BOARD #:" at 3132.02,-1001.53 h25
  text "PCB VIEWED FROM BOTTOM SIDE" at 5608.52,-1001.53 h25
  text "M6 Assembly bottom" at 4560,-1175 h60
  text "LAYER NAME =" at 5309,-1180 h60
  text "IGNORE ->" at 1910.37,-1203.85 h25
  text "TEXAS INSTRUMENTS" at 267.02,-1410.19 h25
  text ".Print_Time" at 1531.52,-1410.19 h25
  text ".Print_Date" at 2260.52,-1410.19 h25
  text "GENERATED    :" at 3130.02,-1410.19 h25
  text ".plot_File_Name" at 4803.02,-1410.19 h25
  text "PLOT NAME =" at 5608.52,-1410.19 h25
M9 Title Sheet:
  drawing of 57 lines, arcs and shapes, not listed
  text "1" at 102.36,7691.14 h70
  text "2" at 2598.02,7691.14 h70
  text "3" at 5087.36,7691.14 h70
  text "4" at 7594.03,7691.14 h70
  text "5" at 10093.02,7691.14 h70
  text "6" at 12598.02,7691.14 h70
  text "A" at -1053.98,6548.14 h70
  text "A" at 13746.02,6548.14 h70
  text "B" at -1053.98,4168.14 h70
  text "B" at 13746.02,4168.14 h70
  text "C" at -1053.98,1793.14 h70
  text "C" at 13746.02,1793.14 h70
  text "PROJECT TITLE:" at 10706.02,-67.86 h45
  text ".PRJ_Title" at 10756.02,-201.19 h70
  text "DESIGNED FOR:" at 10706.02,-368.86 h45
  text ".PRJ_Customer" at 10756.02,-508.86 h70
  text "D" at -1053.98,-576.86 h70
  text "D" at 13746.02,-576.86 h70
  text "FILE NAME:" at 10706.02,-668.86 h45
  text ".PCB_File_Name_No_Path" at 10756.02,-788.86 h70
  text "Texas Instruments (TI) and/or its licensors do not warrant the accuracy or completeness of this specification" at 5736.52,-950.7 h45
  text "ENGINEER:" at 10706.02,-958.86 h45
  text "LAYOUT BY:" at 12211.02,-958.86 h45
  text "or any information contained therein. TI and/or its licensors do not warrant that this design will meet" at 5691.54,-1063.36 h45
  text ".PRJ_Engineer" at 10756.02,-1113.85 h70
  text ".PCB_Layout" at 12261.52,-1113.85 h70
  text "the specifications, will be suitable for your application or fit for any particular purpose, or will operate in" at 5691.54,-1176.03 h45
  text "ALTIUM DESIGNER VERSION:" at 12211.02,-1268.86 h45
  text "an implementation. TI and/or its licensors do not warrant that the design is production worthy. You should" at 5691.54,-1288.69 h45
  text "completely validate and test your design implementation to confirm the system functionality for your application." at 5736.52,-1401.36 h45
  text ".print_Scale" at 10756.02,-1402.19 h70
  text ".Application_BuildNumber" at 12261.52,-1402.19 h70
  text "1" at 102.36,-1608.86 h70
  text "2" at 2598.02,-1608.86 h70
  text "3" at 5087.36,-1608.86 h70
  text "4" at 7594.03,-1608.86 h70
  text "5" at 10093.02,-1608.86 h70
  text "6" at 12598.02,-1608.86 h70
M10 Fab Notes:
  drawing of 227 lines, arcs and shapes, not listed
  text "DESIGN INFORMATION" at 11731.98,6455.36 h60
  text "(REFER ALSO ARRAY/PANEL PROFILING INFORMATION)" at 11380.46,6289.29 h60
  text "BOARD SIZE" at 10694.46,6285 h60
  text "115 MM" at 11160,6170 h60
  text "95 MM" at 11935,6165 h60
  text "X" at 11662.46,6157.18 h60
  text "Number of Layers :" at 11097.46,5960 h60
  text "4" at 12170,5955 h60
  text "8" at 12170.93,5823.21 h60
  text "MIN. TRACK WIDTH:" at 11097.46,5821 h60
  text "MIL" at 12348.46,5821 h60
  text "MIN. CLEARANCE:" at 11097.46,5689 h60
  text "MIL" at 12348.46,5689 h60
  text "7.874" at 12042,5687 h60
  text "12" at 12160.93,5568.21 h60
  text "MIN. VIA DRILL SIZE:" at 11097.46,5557 h60
  text "MIL" at 12348.46,5557 h60
  text "6 MIL ( 0.1524 mm)" at 11792.46,5415.29 h60
  text "MINIMUM ANNULAR RING" at 10768.23,5411.01 h60
  text "EXTERNAL" at 12684,5400 h60
  text "PER" at 10968.23,5293 h60
  text "IPC-D-275 CLASS 2 LEVEL C" at 11188.23,5293 h60
  text "MIL, HOLES" at 12676.46,5180.71 h60
  text "+/-" at 12284,5180 h60
  text "+/-" at 13138,5180 h60
  text "REGISTRATION TOLERANCES:" at 10768.23,5175 h60
  text "METAL" at 11968,5175 h60
  text "5" at 12544.2,5175 h60
  text "3" at 13377.2,5175 h60
  text "MIL" at 13493.46,5175 h60
  text "MATERIAL:" at 10693.46,4965.54 h60
  text "FR-4 High Tg" at 11679.9,4825.21 h60
  text "FR-408" at 11114.46,4816.64 h60
  text "X" at 11521,4817 h60
  text "OTHER" at 12602.46,4816.64 h60
  text "63 MIL (1.6mm) +/-10%" at 11434.56,4653.92 h60
  text "THICKNESS:" at 10768.23,4649.64 h60
  text "X" at 11306.4,4649.64 h60
  text "OTHER" at 12719.46,4649.64 h60
  text "TOLERANCE:" at 10768.23,4491.64 h60
  text "X" at 11607.53,4491.64 h60
  text "ANSI IPC-6012 TYPE 3 CLASS 2" at 11794.48,4491.64 h60
  text "OTHER +/-" at 11794.46,4335.64 h60
  text "BOW & TWIST:" at 10768.23,4178.64 h60
  text "X" at 11607.53,4178.64 h60
  text "ANSI IPC-6012 TYPE 3 CLASS 2" at 11794.48,4178.64 h60
  text "OTHER +/-" at 11794.46,4020.13 h60
  text "COPPER THICKNESS (FINISHED):" at 10693.46,3884.64 h60
  text "1.4MIL (1oz)" at 11573.46,3731.92 h60
  text "2MIL (1.4oz)" at 12340.46,3731.92 h60
  text "2.8MIL (2oz)" at 13067.46,3731.92 h60
  text "OUTER:" at 11050.46,3727.64 h60
  text "X" at 11445,3727 h60
  text "X" at 11445,3582 h60
  text "N/A" at 13067,3575.29 h60
  text "1.4MIL (1oz)" at 11573.46,3574.92 h60
  text "2.8MIL (2oz)" at 12340.46,3574.92 h60
  text "INNER SIGNAL:" at 10761.38,3570.64 h60
  text "DRILLING:" at 10693.46,3431.64 h60
  text "REFERENCE:" at 10768.23,3314.64 h60
  text "X" at 11416.46,3314.64 h60
  text "AS SHOWN" at 11603.46,3314.64 h60
  text "X" at 12317.46,3314.64 h60
  text "NC_DRILL FILES" at 12454.46,3314.64 h60
  text "PTH MIN COPPER THICKNESS:" at 10768.23,3156.64 h60
  text "X" at 12118.46,3156.64 h60
  text "1MIL" at 12255.46,3156.64 h60
  text "OTHER" at 12752.46,3156.64 h60
  text "BOARD FINISH:" at 10693.46,2997.64 h60
  text "SILKSCREEN:" at 10848.68,2879.64 h60
  text "X" at 11797.46,2879.64 h60
  text "TOP" at 11923.46,2879.64 h60
  text "X" at 12307.46,2879.64 h60
  text "BOTTOM" at 12434.46,2879.64 h60
  text "SILKSCREEN COLOR:" at 10848.68,2712.64 h60
  text "X" at 11796.42,2712.64 h60
  text "WHITE" at 11923.46,2712.64 h60
  text "OTHER" at 12434.46,2712.64 h60
  text "SOLDER RESIST COLOR:" at 10848.68,2542.64 h60
  text "X" at 11416.42,2383.44 h60
  text "GREEN" at 11543.46,2383.44 h60
  text "BLUE" at 12134.46,2383.44 h60
  text "OTHER" at 12672.46,2383.44 h60
  text "IMMERSION GOLD (ENIG)" at 11754.46,2194.92 h60
  text "ENEPIG" at 13092,2191.64 h60
  text "SURFACE FINISH:" at 10693.46,2190.64 h60
  text "X" at 11567.51,2190.64 h60
  text "IMM. TIN/SILVER OR EQUIV" at 11023,2033.64 h60
  text "OTHER" at 12454.46,2033.64 h60
  text "ARRAY/PANEL:" at 10693.46,1854.64 h60
  text "CUT AND TRIM PER MECH LAYER 1" at 11754.46,1850.35 h60
  text "N.C. ROUTE" at 11754.46,1698.64 h60
  text "X" at 12433.46,1698.64 h60
  text "V. SCORE" at 12620.46,1698.64 h60
  text "CERTIFICATION:" at 10693.46,1561.64 h60
  text "MATERIALS AND WORKMANSHIP FOR ALL PCBS" at 11418.46,1561.64 h60
  text "TO MEET OR EXCEED THE REQUIREMENTS OF:" at 11418.46,1463.64 h60
  text "X" at 11044.96,1327.14 h60
  text "ANSI IPC-A-600F CLASS ->" at 11183.96,1327.14 h60
  text "X" at 12823.02,1327.14 h60
  text "2" at 12941.96,1327.14 h60
  text "1" at 12626.96,1325.64 h60
  text "3" at 13295.96,1325.64 h60
  text "X" at 11047.02,1167.64 h60
  text "UL 94V-0" at 11183.96,1167.64 h60
  text "X" at 11859.02,1167.64 h60
  text "RoHS" at 11995.96,1167.64 h60
  text "OTHER" at 12640.36,1167.64 h60
  text "PER ORDER" at 13037.42,1167.64 h60
  text "VIA TENTING:" at 11911,1034 h60
  text "X" at 12671,1032 h60
  text "ADDITIONAL REQUIREMENTS:" at 10693.46,1026.64 h60
  text "YES" at 12460.67,1024.92 h60
  text "NO" at 12825.47,1019.69 h60
  text "MICROSECTION:" at 10768.23,911.64 h60
  text "YES" at 11673.96,911.64 h60
  text "IMPEDANCE CONTROL:" at 11933,905 h60
  text "YES" at 12917,904 h60
  text "X" at 13459,897 h60
  text "NO" at 13292.47,886.69 h60
  text "REQUIRED" at 12535.46,755.5 h60
  text "BARE BOARD ELEC. TEST:" at 10768.23,752.64 h60
  text "NONE" at 12073.96,752.64 h60
  text "X" at 12408.46,752.64 h60
  text "PER ORDER" at 13127.46,752.64 h60
  text "MANUFACTURER'S UL:" at 10768.23,595.64 h60
  text "RAIL" at 11933.96,591.35 h60
  text "METAL" at 12425.77,591.35 h60
  text "SILK" at 12937.46,591.35 h60
  text "X" at 12801,591 h60
M11 Gerber Information:
  lines w10: -929.48,-1275.53 5670.52,-1275.53 ; -929.48,-1072.19 5672.52,-1072.19 ; -929.48,-868.86 -929.48,-1478.86 3075.52,-1478.86 5672.52,-1478.86 5672.52,-868.86 -928.98,-868.86 -928.98,-1478.86 646.52,-1478.86 ; 1535.52,-1478.86 1535.52,-868.86 ; 2802.52,-1072.19 2802.52,-868.86 ; 3642.52,-1072.19 3642.52,-868.86 ; 4264.52,-1485.36 4264.52,-1282.53
  text "ALL ARTWORK VIEWED FROM TOP SIDE" at -865.98,-1001.03 h60
  text "BOARD #:" at 1610.52,-1001.03 h60
  text ".PRJ_Number" at 2156.02,-1001.03 h40
  text "REV:" at 3000.52,-1001.03 h60
  text ".PCB_Rev" at 3292.02,-1001.03 h60
  text "SVN REV:" at 3838.52,-1001.03 h60
  text ".VersionControl_RevNumber" at 4344.52,-1001.03 h60
  text "LAYER NAME =" at -865.98,-1203.85 h60
  text "PLOT NAME =" at -865.98,-1409.69 h60
  text ".plot_File_Name" at -60.48,-1409.69 h60
  text "GENERATED    :" at 1612.52,-1409.69 h60
  text ".Print_Date" at 2482.02,-1409.69 h60
  text ".Print_Time" at 3211.02,-1409.69 h60
  text "TEXAS INSTRUMENTS" at 4475.52,-1409.69 h60
M12 Stackup:
  lines w6: 10908.98,7243.36 13458.98,7243.36 ; 10908.98,7347.76 13458.98,7347.76 ; 10848.98,6758.36 ccw(c10882.98,6758.36) 10882.98,6724.36 13484.98,6724.36 ccw(c13484.98,6758.36) 13518.98,6758.36 13518.98,7464.36 ccw(c13484.98,7464.36) 13484.98,7498.36 10882.98,7498.36 ccw(c10882.98,7464.36) 10848.98,7464.36 10848.98,6758.36
  text "Layer Stack Up Detail for: TIDA-00810-E2.Pcbdoc" at 10908.98,7380.46 h57
  text "Layer" at 10908.98,7308.76 h24
  text "Gerber" at 11804.79,7308.76 h24
  text "Copper" at 12368.31,7308.76 h24
  text "Dielectric" at 12971.02,7308.76 h24
  text "Name" at 10908.98,7260.76 h24
  text "Document" at 11804.79,7260.76 h24
  text "Thickness" at 12368.31,7260.76 h24
  text "Material" at 12971.02,7260.76 h24
  text "Top Solder Mask" at 10923.98,7169.36 h34
  text "(.GTS)" at 11804.79,7167.8 h34
  text "Solder Resist" at 12971.02,7167.8 h34
  text "Top Layer" at 10918.98,7074.36 h34
  text "(.GTL)" at 11804.79,7071.05 h34
  text "1.4mil" at 12368.31,7071.05 h34
  text "FR4-High Tg" at 12999.98,7070.36 h34
  text "FR4-High Tg" at 13004.98,7015.36 h34
  text "1.4mil" at 12368.31,7006.05 h34
  text "GND" at 10917.98,7002.36 h34
  text "(.G1)" at 11803.79,6994.05 h34
  text "FR4-High Tg" at 13004.98,6940.36 h34
  text "1.4mil" at 12368.31,6936.05 h34
  text "(.G2)" at 11803.79,6924.05 h34
  text "PWR" at 10917.98,6922.36 h34
  text "FR4-High Tg" at 13004.98,6845.36 h34
  text "Bottom Layer" at 10913.98,6844.36 h34
  text "(.GBL)" at 11812.98,6840.36 h34
  text "1.4mil" at 12372.98,6834.36 h34
  text "Solder Resist" at 12964.98,6767.36 h34
  text "(.GBS)" at 11809.98,6760.36 h34
  text "Bottom Solder Mask" at 10918.98,6759.36 h34
M13 Component Bodies Top:
  text ".Layer_Name" at -60.48,-1203.85 h60
M14 Component Bodies Bottom:
  text ".Layer_Name" at -60.48,-1203.85 h60
M15 Courtyards Top:
  text ".Layer_Name" at -60.48,-1203.85 h60
M16 Courtyards Bottom:
  text ".Layer_Name" at -60.48,-1203.85 h60
Drill Drawing:
  circle w10: c5503.8,2343.05 r16.59
  circle w10: c5503.8,2343.05 r27.66
  lines w10: 5476.14,1333.55 5489.97,1333.55 5489.97,1319.72 5517.63,1319.72 5517.63,1333.55 5531.46,1333.55 5531.46,1361.21 5517.63,1361.21 5517.63,1375.04 5489.97,1375.04 5489.97,1361.21 5476.14,1361.21 5476.14,1333.55 ; 5476.14,1458.01 5489.97,1458.01 5503.8,1444.18 5517.63,1458.01 5531.46,1458.01 5517.63,1471.84 5531.46,1485.67 5517.63,1485.67 5503.8,1499.5 5489.97,1485.67 5476.14,1485.67 5489.97,1471.84 5476.14,1458.01 ; 5476.14,1623.96 5531.46,1623.96 5503.8,1568.64 5476.14,1623.96 ; 5476.14,1706.93 5489.97,1706.93 5503.8,1693.1 5517.63,1706.93 5531.46,1706.93 5517.63,1720.76 5531.46,1734.59 5517.63,1734.59 5503.8,1748.41 5489.97,1734.59 5476.14,1734.59 5489.97,1720.76 5476.14,1706.93 ; 5476.14,1845.22 5503.8,1817.56 5531.46,1845.22 5503.8,1872.87 5476.14,1845.22 ; 5476.14,1942.02 5503.8,1955.85 5531.46,1942.02 5517.63,1969.67 5531.46,1997.33 5503.8,1983.5 5476.14,1997.33 5489.97,1969.67 5476.14,1942.02 ; 5476.14,2121.79 5531.46,2121.79 5503.8,2066.48 5476.14,2121.79 ; 5476.14,2190.93 5503.8,2204.76 5531.46,2190.93 5517.63,2218.59 5531.46,2246.25 5503.8,2232.42 5476.14,2246.25 5489.97,2218.59 5476.14,2190.93 ; 5476.14,2439.85 5531.46,2439.85 5531.46,2495.17 5476.14,2495.17 5476.14,2439.85 ; 5487.21,1339.08 5495.5,1339.08 5495.5,1330.79 5512.1,1330.79 5512.1,1339.08 5520.39,1339.08 5520.39,1355.68 5512.1,1355.68 5512.1,1363.98 5495.5,1363.98 5495.5,1355.68 5487.21,1355.68 5487.21,1339.08 ; 5487.21,1712.46 5495.5,1712.46 5503.8,1704.16 5512.1,1712.46 5520.39,1712.46 5512.1,1720.76 5520.39,1729.05 5512.1,1729.05 5503.8,1737.35 5495.5,1729.05 5487.21,1729.05 5495.5,1720.76 5487.21,1712.46 ; 5487.21,1953.08 5503.8,1961.38 5520.39,1953.08 5512.1,1969.67 5520.39,1986.27 5503.8,1977.97 5487.21,1986.27 5495.5,1969.67 5487.21,1953.08 ; 5487.21,2110.73 5520.39,2110.73 5503.8,2077.54 5487.21,2110.73 ; 5487.21,2450.91 5520.39,2450.91 5520.39,2484.1 5487.21,2484.1 5487.21,2450.91
  lines w12: 5426,1282.39 9428.62,1282.39 ; 5426,2775.89 9428.62,2775.89 ; 5764.17,1157.93 5764.17,2900.35 ; 6096.28,1157.93 6096.28,2900.35 ; 6733.29,1157.93 6733.29,2900.35 ; 6992.64,1157.93 6992.64,2900.35 ; 7368.06,1157.93 7368.06,2900.35 ; 8091.91,1157.93 8091.91,2900.35 ; 8769.69,1157.93 8769.69,2900.35 ; 5426,1157.93 9428.62,1157.93 9428.62,2900.35 5426,2900.35 5426,1157.93
  text "Drill Table" at 5425,2950 h60
  text "Symbol" at 5500.68,2813.23 h72
  text "Quantity" at 5801.51,2813.23 h72
  text "Finished Hole Size" at 6133.62,2813.23 h72
  text "Plated" at 6770.62,2813.23 h72
  text "Hole Type" at 7029.98,2813.23 h72
  text "Drill Layer Pair" at 7405.4,2813.23 h72
  text "Routed Path Length" at 8129.25,2813.23 h72
  text "Hole Length" at 8807.02,2813.23 h72
  text "309" at 5801.51,2688.77 h60
  text "12.00mil (0.305mm)" at 6133.62,2688.77 h60
  text "PTH" at 6770.62,2688.77 h60
  text "Round" at 7029.98,2688.77 h60
  text "Top Layer - Bottom Layer" at 7405.4,2688.77 h60
  text "-" at 8129.25,2688.77 h60
  text "-" at 8807.02,2688.77 h60
  text "A" at 5475.37,2678.78 h55.31
  text "35" at 5801.51,2564.31 h60
  text "16.00mil (0.406mm)" at 6133.62,2564.31 h60
  text "PTH" at 6770.62,2564.31 h60
  text "Round" at 7029.98,2564.31 h60
  text "Top Layer - Bottom Layer" at 7405.4,2564.31 h60
  text "-" at 8129.25,2564.31 h60
  text "-" at 8807.02,2564.31 h60
  text "B" at 5475.37,2554.32 h55.31
  text "12" at 5801.51,2439.85 h60
  text "17.72mil (0.450mm)" at 6133.62,2439.85 h60
  text "PTH" at 6770.62,2439.85 h60
  text "Round" at 7029.98,2439.85 h60
  text "Top Layer - Bottom Layer" at 7405.4,2439.85 h60
  text "-" at 8129.25,2439.85 h60
  text "-" at 8807.02,2439.85 h60
  text "9" at 5801.51,2315.39 h60
  text "35.04mil (0.890mm)" at 6133.62,2315.39 h60
  text "PTH" at 6770.62,2315.39 h60
  text "Round" at 7029.98,2315.39 h60
  text "Top Layer - Bottom Layer" at 7405.4,2315.39 h60
  text "-" at 8129.25,2315.39 h60
  text "-" at 8807.02,2315.39 h60
  text "18" at 5801.51,2190.93 h60
  text "40.00mil (1.016mm)" at 6133.62,2190.93 h60
  text "PTH" at 6770.62,2190.93 h60
  text "Round" at 7029.98,2190.93 h60
  text "Top Layer - Bottom Layer" at 7405.4,2190.93 h60
  text "-" at 8129.25,2190.93 h60
  text "-" at 8807.02,2190.93 h60
  text "10" at 5801.51,2066.48 h60
  text "44.00mil (1.118mm)" at 6133.62,2066.48 h60
  text "PTH" at 6770.62,2066.48 h60
  text "Round" at 7029.98,2066.48 h60
  text "Top Layer - Bottom Layer" at 7405.4,2066.48 h60
  text "-" at 8129.25,2066.48 h60
  text "-" at 8807.02,2066.48 h60
  text "20" at 5801.51,1942.02 h60
  text "45.28mil (1.150mm)" at 6133.62,1942.02 h60
  text "PTH" at 6770.62,1942.02 h60
  text "Round" at 7029.98,1942.02 h60
  text "Top Layer - Bottom Layer" at 7405.4,1942.02 h60
  text "-" at 8129.25,1942.02 h60
  text "-" at 8807.02,1942.02 h60
  text "10" at 5801.51,1817.56 h60
  text "49.21mil (1.250mm)" at 6133.62,1817.56 h60
  text "PTH" at 6770.62,1817.56 h60
  text "Round" at 7029.98,1817.56 h60
  text "Top Layer - Bottom Layer" at 7405.4,1817.56 h60
  text "-" at 8129.25,1817.56 h60
  text "-" at 8807.02,1817.56 h60
  text "4" at 5801.51,1693.1 h60
  text "80.71mil (2.050mm)" at 6133.62,1693.1 h60
  text "PTH" at 6770.62,1693.1 h60
  text "Round" at 7029.98,1693.1 h60
  text "Top Layer - Bottom Layer" at 7405.4,1693.1 h60
  text "-" at 8129.25,1693.1 h60
  text "-" at 8807.02,1693.1 h60
  text "2" at 5801.51,1568.64 h60
  text "120.00mil (3.048mm)" at 6133.62,1568.64 h60
  text "NPTH" at 6770.62,1568.64 h60
  text "Slot" at 7029.98,1568.64 h60
  text "Top Layer - Bottom Layer" at 7405.4,1568.64 h60
  text "274.00mil (6.960mm)" at 8129.25,1568.64 h60
  text "394.00mil (10.008mm)" at 8807.02,1568.64 h60
  text "1" at 5801.51,1444.18 h60
  text "120.00mil (3.048mm)" at 6133.62,1444.18 h60
  text "NPTH" at 6770.62,1444.18 h60
  text "Slot" at 7029.98,1444.18 h60
  text "Top Layer - Bottom Layer" at 7405.4,1444.18 h60
  text "430.00mil (10.922mm)" at 8129.25,1444.18 h60
  text "550.00mil (13.970mm)" at 8807.02,1444.18 h60
  text "4" at 5801.51,1319.72 h60
  text "125.98mil (3.200mm)" at 6133.62,1319.72 h60
  text "PTH" at 6770.62,1319.72 h60
  text "Round" at 7029.98,1319.72 h60
  text "Top Layer - Bottom Layer" at 7405.4,1319.72 h60
  text "-" at 8129.25,1319.72 h60
  text "-" at 8807.02,1319.72 h60
  text "434 Total" at 5801.51,1195.26 h60
  text "Slot definitions :" at 5500.68,1108.14 h60
  text "Routed Path Length" at 5951.08,1108.14 h60
  text "= Calculated from tool start centre position to tool end centre position." at 6490.29,1108.14 h60
  text "Hole Length" at 5951.08,1058.36 h60
  text "= Routed Path Length + Tool Size = Slot length as defined in the PCB layout" at 6290.69,1058.36 h60
  text "FOR 12MIL DRILL +0/-12MIL" at 5440,905 h60
  text "FOR PTH DRILL +/-3MIL" at 5440,785 h60
  text "FOR NPTH DRILL +/-2MIL" at 5440,655 h60
  text "FOR 16MIL DRILL +0/-16MIL" at 5440,540 h60
  text ".Layer_Name" at -25,-1200 h60

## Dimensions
0,3740.16 to 4527.56,3740.16 on M2 Board Dimensions
0,0 to 0,3740.16 on M2 Board Dimensions
-637.48,-755.86 to 362.52,-755.86 on M2 Board Dimensions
